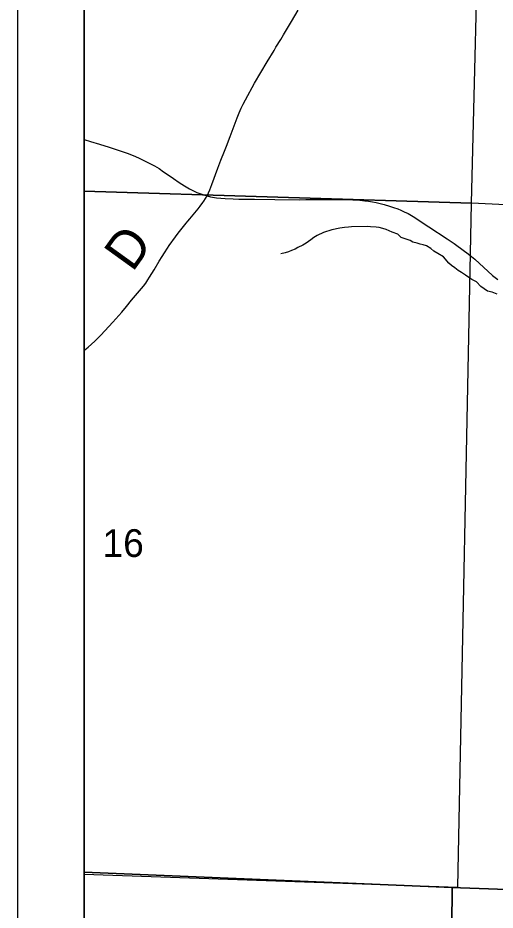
# Model space of a CAD drawing. Extents: x 0 to 34, y 0 to 22.
# Drawn here: x 2.5 to 3.221, y 16.635 to 17.981 of the extents above; entities that cross this region are included whole.
import ezdxf

# ---------------------------------------------------------------- set-up
doc = ezdxf.new("R2010")
doc.units = 0
for name, color, linetype in [('GM_X_Corporation', 7, 'Continuous'), ('GM_X_County', 7, 'Continuous'), ('GM_X_County_Road', 7, 'Continuous'), ('GM_X_County_Road_Text', 7, 'Continuous'), ('GM_X_Minor_River', 7, 'Continuous'), ('GM_X_Section_Text', 7, 'Continuous'), ('GM_X_Township_Road', 7, 'Continuous'), ('SH_Data', 7, 'Continuous')]:
    doc.layers.add(name, color=color, linetype=linetype)

msp = doc.modelspace()

# ---------------------------------------------------------------- linework, layer by layer
at = {"layer": 'GM_X_Corporation'}
for points in [[(9.4, 16.4853), (9.4, 20.4), (2.6, 20.4), (2.6, 16.6918), (3.1555, 16.6686), (3.1684, 16.6682), (4.0515, 16.6368), (4.1011, 16.6362), (4.1867, 16.6352), (4.5473, 16.6256), (4.6351, 16.6229), (5.4202, 16.5982), (6.0834, 16.5816), (6.2194, 16.578), (8.0963, 16.5226), (9.09, 16.4927)], [(6.2895, 20.4), (2.6, 20.4), (2.6, 16.6918), (3.1555, 16.6686), (3.1684, 16.6682), (4.0515, 16.6368), (4.1011, 16.6362), (4.1867, 16.6352), (4.5473, 16.6256), (4.6351, 16.6229), (5.4202, 16.5982), (6.0834, 16.5816), (6.2194, 16.578), (6.2729, 18.2077), (6.2744, 18.4654), (6.2786, 18.5898), (6.292, 18.5898), (6.2926, 19.1539), (6.2942, 19.6131), (6.2595, 19.6124)], [(2.6, 18.7322), (2.6, 17.7192), (3.1848, 17.7013), (3.2101, 18.7098)], [(4.2417, 18.6679), (4.2074, 17.6513), (3.1848, 17.7013), (3.2101, 18.7098)], [(2.6, 17.7192), (2.6, 16.6889), (3.1641, 16.6693), (3.1848, 17.7013)], [(2.6, 16.6918), (2.6, 13.6), (9.4, 13.6), (9.4, 16.4853), (9.09, 16.4927), (8.0963, 16.5226), (6.2194, 16.578), (6.0834, 16.5816), (5.4202, 16.5982), (4.6351, 16.6229), (4.5473, 16.6256), (4.1867, 16.6352), (4.1011, 16.6362), (4.0515, 16.6368), (3.1684, 16.6682), (3.1555, 16.6686)], [(2.6, 16.6918), (2.6, 13.6417), (3.0575, 13.6324), (3.1025, 13.6315), (3.1033, 13.7653), (3.1089, 14.0542), (3.109, 14.0614), (3.1121, 14.2169), (3.1127, 14.2486), (3.1134, 14.2853), (3.1142, 14.3277), (3.1263, 14.9513), (3.1401, 15.483), (3.148, 15.8071), (3.1555, 16.6686)]]:
    msp.add_lwpolyline(points, close=True, dxfattribs=at)
msp.add_lwpolyline([(4.5473, 16.6256), (4.1867, 16.6352), (4.1011, 16.6362), (4.0515, 16.6368), (3.1684, 16.6682), (3.1555, 16.6686), (3.148, 15.8071)], dxfattribs=at)
at = {"layer": 'GM_X_County'}
msp.add_lwpolyline([(9.4, 16.4853), (9.09, 16.4927), (8.0963, 16.5226), (6.2194, 16.578), (6.0834, 16.5816), (5.4202, 16.5982), (4.6351, 16.6229), (4.5473, 16.6256), (4.1867, 16.6352), (4.1011, 16.6362), (4.0515, 16.6368), (3.1684, 16.6682), (3.1555, 16.6686), (2.6, 16.6918)], dxfattribs=at)
at = {"layer": 'GM_X_County_Road'}
msp.add_lwpolyline([(2.6, 17.4794), (2.6012, 17.4802), (2.606, 17.4839), (2.6162, 17.4929), (2.6204, 17.4973), (2.6252, 17.5023), (2.6436, 17.5218), (2.6572, 17.5371), (2.6639, 17.5452), (2.6718, 17.555), (2.6896, 17.5762), (2.693, 17.5807), (2.6962, 17.5855), (2.6989, 17.5898), (2.7058, 17.6007), (2.7133, 17.6136), (2.7177, 17.6207), (2.7214, 17.6265), (2.7259, 17.6335), (2.7285, 17.6373), (2.7382, 17.6507), (2.7423, 17.6561), (2.7542, 17.6714), (2.7568, 17.6744), (2.7595, 17.6776), (2.7622, 17.6806), (2.7724, 17.6927), (2.7753, 17.6968), (2.7791, 17.7021), (2.781, 17.7046), (2.7834, 17.7083), (2.7856, 17.7123), (2.7898, 17.7215), (2.7929, 17.7296), (2.8022, 17.7541), (2.8067, 17.7664), (2.8119, 17.7798), (2.8162, 17.7901), (2.8183, 17.7956), (2.8207, 17.8018), (2.8312, 17.8303), (2.8343, 17.8377), (2.8372, 17.8445), (2.8402, 17.8507), (2.8437, 17.8573), (2.8575, 17.8822), (2.8763, 17.9148), (2.8868, 17.9316), (2.8896, 17.9365), (2.897, 17.9483), (2.9013, 17.9552), (2.9073, 17.9656), (2.9133, 17.9756), (2.9234, 17.9925)], dxfattribs=at)
at = {"layer": 'GM_X_Minor_River'}
msp.add_lwpolyline([(3.2237, 17.5639), (3.2161, 17.5672), (3.2093, 17.5686), (3.199, 17.5757), (3.1925, 17.5824), (3.1852, 17.5861), (3.181, 17.589), (3.1761, 17.5927), (3.1696, 17.5968), (3.165, 17.5998), (3.1596, 17.6039), (3.1547, 17.6072), (3.1505, 17.6109), (3.1428, 17.6202), (3.134, 17.6254), (3.1283, 17.6291), (3.1237, 17.6328), (3.1172, 17.6369), (3.1119, 17.6383), (3.1074, 17.6394), (3.1028, 17.6408), (3.0964, 17.6426), (3.0922, 17.6449), (3.0876, 17.6467), (3.0789, 17.6496), (3.0735, 17.6544), (3.0651, 17.6577), (3.056, 17.6614), (3.0511, 17.6632), (3.0454, 17.6646), (3.0408, 17.665), (3.0325, 17.6656), (3.0279, 17.6659), (3.0037, 17.6656), (2.9992, 17.6652), (2.9931, 17.6648), (2.9863, 17.6635), (2.9742, 17.6611), (2.9614, 17.6572), (2.952, 17.6526), (2.9468, 17.6495), (2.9422, 17.646), (2.9355, 17.6411), (2.9302, 17.638), (2.9227, 17.6345), (2.9186, 17.6318), (2.9133, 17.6298), (2.9084, 17.6279), (2.9035, 17.6263), (2.8971, 17.6251)], dxfattribs=at)
at = {"layer": 'GM_X_Township_Road'}
for points in [[(2.6, 17.7975), (2.6095, 17.7946), (2.6232, 17.7905), (2.638, 17.7859), (2.6516, 17.7814), (2.6653, 17.7768), (2.6743, 17.7734), (2.682, 17.7699), (2.6902, 17.7659), (2.6981, 17.7618), (2.7062, 17.7576), (2.7135, 17.7534), (2.7201, 17.7488), (2.7272, 17.7439), (2.7351, 17.7385), (2.7437, 17.7326), (2.7514, 17.7277), (2.7594, 17.723), (2.7651, 17.7198), (2.7703, 17.7175), (2.7761, 17.7153), (2.7808, 17.7137), (2.7856, 17.7123)], [(2.7856, 17.7123), (2.7908, 17.711), (2.7969, 17.7098), (2.7997, 17.7093), (2.8066, 17.7087), (2.8128, 17.7082), (2.8253, 17.7077), (2.8337, 17.7075), (2.8433, 17.7073), (2.8573, 17.7072), (2.8879, 17.707), (2.9258, 17.7066), (2.9349, 17.7067), (2.9658, 17.7071), (2.9884, 17.707), (3.0058, 17.7065), (3.0105, 17.7063), (3.0164, 17.7059), (3.0241, 17.7051), (3.0295, 17.7043), (3.0353, 17.7034), (3.0412, 17.7023), (3.047, 17.7009), (3.0532, 17.6992), (3.0612, 17.6969), (3.0671, 17.695), (3.0735, 17.6927), (3.078, 17.6909), (3.0834, 17.6884), (3.0891, 17.6856), (3.0941, 17.6829), (3.0992, 17.6798), (3.1118, 17.6712), (3.1203, 17.6655), (3.1483, 17.6475), (3.1588, 17.6404), (3.1746, 17.6291), (3.178, 17.6264), (3.1848, 17.6209), (3.1899, 17.6166), (3.2165, 17.5924), (3.2206, 17.5891), (3.2246, 17.5863)]]:
    msp.add_lwpolyline(points, dxfattribs=at)
at = {"layer": 'SH_Data'}
for points in [[(2.5, 20.5), (9.5, 20.5), (9.5, 13.5), (2.5, 13.5)], [(2.6, 20.4), (9.4, 20.4), (9.4, 13.6), (2.6, 13.6)]]:
    msp.add_lwpolyline(points, close=True, dxfattribs=at)

# ---------------------------------------------------------------- texts
at = {"layer": 'GM_X_County_Road_Text'}
msp.add_text('D', height=0.0568, rotation=54.2474, dxfattribs=at).set_placement((2.673, 17.5959))
at = {"layer": 'GM_X_Section_Text'}
msp.add_text('16', height=0.04186, rotation=0, dxfattribs=at).set_placement((2.6279, 17.1675))

doc.saveas('drawing.dxf')
